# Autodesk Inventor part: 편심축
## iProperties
Manager: 한국ATC센터
Company: 한국ATC센터
Created: 2014-07
Part Number: 편심축
Document SubType Name: Modeling
Designer: KYOUNG IL JANG
Density: 7.86 g/cm^3
Material: 강, 연강
Mass: 1544.74 g
Surface Area: 256.354 cm^2
Volume: 196.531 cm^3
Author: KYOUNG IL JANG
